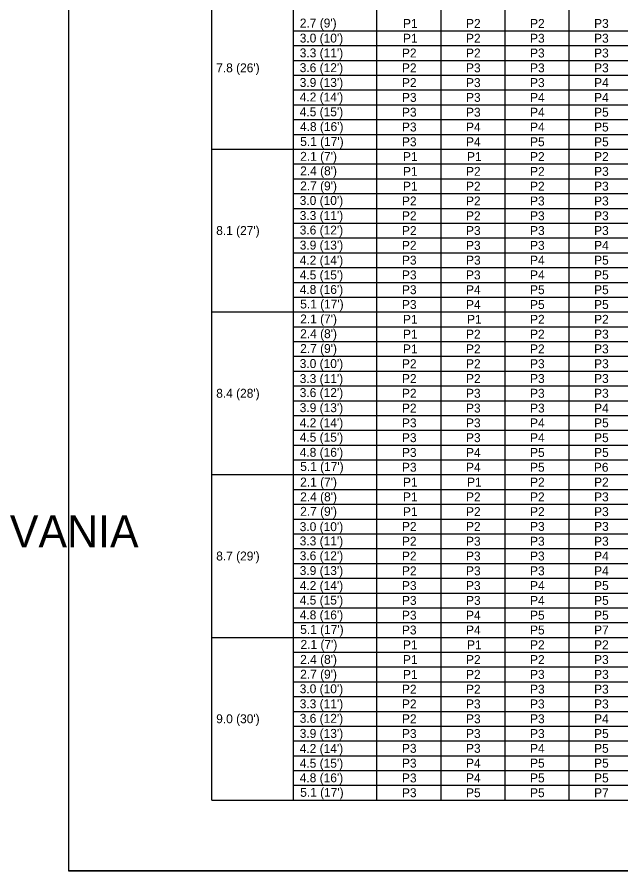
# Model space of a CAD drawing. Extents: x 637580 to 641008, y 294594 to 295782.
# Drawn here: x 640126.1 to 640328.9, y 295202.6 to 295489.6 of the extents above; entities that cross this region are included whole.
import ezdxf

# ---------------------------------------------------------------- set-up
doc = ezdxf.new("R2010")
doc.units = 0
doc.layers.add('1', color=7, linetype='Continuous')
doc.layers.add('2', color=7, linetype='Continuous')

msp = doc.modelspace()

# ---------------------------------------------------------------- linework, layer by layer
at = {"layer": '1'}
for p, q in [((640143.31, 295766.63), (640143.31, 295202.63)), ((640191.43, 295226.43), (640191.43, 295743.08)), ((640218.95, 295226.43), (640218.95, 295735.41)), ((640191.43, 295445.22), (640526.66, 295445.22)), ((640191.43, 295390.52), (640526.66, 295390.52)), ((640191.43, 295335.82), (640526.66, 295335.82)), ((640191.43, 295281.12), (640526.66, 295281.12)), ((640191.43, 295226.43), (640526.66, 295226.43)), ((640929.31, 295202.63), (640143.31, 295202.63)), ((640143.31, 295202.63), (640729.31, 295202.63))]:
    msp.add_line(p, q, dxfattribs=at)
at = {"layer": '2'}
for p, q in [((640246.95, 295226.43), (640246.95, 295735.41)), ((640268.47, 295226.43), (640268.47, 295728.06)), ((640289.99, 295226.43), (640289.99, 295728.06)), ((640311.5, 295226.43), (640311.5, 295728.06)), ((640218.95, 295485), (640526.66, 295485)), ((640218.95, 295480.02), (640526.66, 295480.02)), ((640218.95, 295475.05), (640526.66, 295475.05)), ((640218.95, 295470.08), (640526.66, 295470.08)), ((640218.95, 295465.11), (640526.66, 295465.11)), ((640218.95, 295460.13), (640526.66, 295460.13)), ((640218.95, 295455.16), (640526.66, 295455.16)), ((640218.95, 295450.19), (640526.66, 295450.19)), ((640218.95, 295440.24), (640526.66, 295440.24)), ((640218.95, 295435.27), (640526.66, 295435.27)), ((640218.95, 295430.3), (640526.66, 295430.3)), ((640218.95, 295425.33), (640526.66, 295425.33)), ((640218.95, 295420.35), (640526.66, 295420.35)), ((640218.95, 295415.38), (640526.66, 295415.38)), ((640218.95, 295410.41), (640526.66, 295410.41)), ((640218.95, 295405.44), (640526.66, 295405.44)), ((640218.95, 295400.46), (640526.66, 295400.46)), ((640218.95, 295395.49), (640526.66, 295395.49)), ((640218.95, 295385.55), (640526.66, 295385.55)), ((640218.95, 295380.57), (640526.66, 295380.57)), ((640218.95, 295375.6), (640526.66, 295375.6)), ((640218.95, 295370.63), (640526.66, 295370.63)), ((640218.95, 295365.66), (640526.66, 295365.66)), ((640218.95, 295360.68), (640526.66, 295360.68)), ((640218.95, 295355.71), (640526.66, 295355.71)), ((640218.95, 295350.74), (640526.66, 295350.74)), ((640218.95, 295345.77), (640526.66, 295345.77)), ((640218.95, 295340.79), (640526.66, 295340.79)), ((640218.95, 295330.85), (640526.66, 295330.85)), ((640218.95, 295325.88), (640526.66, 295325.88)), ((640218.95, 295320.9), (640526.66, 295320.9)), ((640218.95, 295315.93), (640526.66, 295315.93)), ((640218.95, 295310.96), (640526.66, 295310.96)), ((640218.95, 295305.99), (640526.66, 295305.99)), ((640218.95, 295301.01), (640526.66, 295301.01)), ((640218.95, 295296.04), (640526.66, 295296.04)), ((640218.95, 295291.07), (640526.66, 295291.07)), ((640218.95, 295286.1), (640526.66, 295286.1)), ((640218.95, 295276.15), (640526.66, 295276.15)), ((640218.95, 295271.18), (640526.66, 295271.18)), ((640218.95, 295266.21), (640526.66, 295266.21)), ((640218.95, 295261.23), (640526.66, 295261.23)), ((640218.95, 295256.26), (640526.66, 295256.26)), ((640218.95, 295251.29), (640526.66, 295251.29)), ((640218.95, 295246.32), (640526.66, 295246.32)), ((640218.95, 295241.34), (640526.66, 295241.34)), ((640218.95, 295236.37), (640526.66, 295236.37)), ((640218.95, 295231.4), (640526.66, 295231.4))]:
    msp.add_line(p, q, dxfattribs=at)

# ---------------------------------------------------------------- texts
at = {"layer": '1'}
for s, height, p in [("2.7 (9')", 3, (640221.04, 295486.11)), ('P1', 3, (640255.7, 295485.98)), ('P2', 3, (640276.88, 295485.98)), ('P2', 3, (640298.39, 295485.98)), ('P3', 3, (640319.91, 295485.98)), ("3.0 (10')", 3, (640221.01, 295481.06)), ('P1', 3, (640255.7, 295481.01)), ('P2', 3, (640276.88, 295481.01)), ('P3', 3, (640298.39, 295481.01)), ('P3', 3, (640319.91, 295481.01)), ("3.3 (11')", 3, (640221.01, 295476.08)), ('P2', 3, (640255.36, 295476.04)), ('P2', 3, (640276.88, 295476.04)), ('P3', 3, (640298.39, 295476.04)), ('P3', 3, (640319.91, 295476.04)), ("3.6 (12')", 3, (640221.01, 295471.11)), ("7.8 (26')", 3, (640192.95, 295471.06)), ('P2', 3, (640255.36, 295471.06)), ('P3', 3, (640276.88, 295471.06)), ('P3', 3, (640298.39, 295471.06)), ('P3', 3, (640319.91, 295471.06)), ("3.9 (13')", 3, (640221.01, 295466.14)), ('P2', 3, (640255.36, 295466.09)), ('P3', 3, (640276.88, 295466.09)), ('P3', 3, (640298.39, 295466.09)), ('P4', 3, (640319.91, 295466.09)), ("4.2 (14')", 3, (640221.01, 295461.25)), ('P3', 3, (640255.36, 295461.12)), ('P3', 3, (640276.88, 295461.12)), ('P4', 3, (640298.39, 295461.12)), ('P4', 3, (640319.91, 295461.12)), ("4.5 (15')", 3, (640221.01, 295456.28)), ('P3', 3, (640255.36, 295456.15)), ('P3', 3, (640276.88, 295456.15)), ('P4', 3, (640298.39, 295456.15)), ('P5', 3, (640319.91, 295456.15)), ("4.8 (16')", 3, (640221.1, 295451.3)), ('P3', 3, (640255.36, 295451.17)), ('P4', 3, (640276.88, 295451.17)), ('P4', 3, (640298.39, 295451.17)), ('P5', 3, (640319.91, 295451.17)), ("5.1 (17')", 3, (640221.17, 295446.28)), ('P3', 3, (640255.36, 295446.2)), ('P4', 3, (640276.88, 295446.2)), ('P5', 3, (640298.39, 295446.2)), ('P5', 3, (640319.91, 295446.2)), ("2.1 (7')", 3, (640221.16, 295441.31)), ('P1', 3, (640255.7, 295441.23)), ('P1', 3, (640277.22, 295441.23)), ('P2', 3, (640298.39, 295441.23)), ('P2', 3, (640319.91, 295441.23)), ("2.4 (8')", 3, (640221.16, 295436.43)), ('P1', 3, (640255.7, 295436.26)), ('P2', 3, (640276.88, 295436.26)), ('P2', 3, (640298.39, 295436.26)), ('P3', 3, (640319.91, 295436.26)), ("2.7 (9')", 3, (640221.16, 295431.37)), ('P1', 3, (640255.7, 295431.28)), ('P2', 3, (640276.88, 295431.28)), ('P2', 3, (640298.39, 295431.28)), ('P3', 3, (640319.91, 295431.28)), ("3.0 (10')", 3, (640221.01, 295426.48)), ('P2', 3, (640255.36, 295426.31)), ('P2', 3, (640276.88, 295426.31)), ('P3', 3, (640298.39, 295426.31)), ('P3', 3, (640319.91, 295426.31)), ("3.3 (11')", 3, (640221.01, 295421.43)), ('P2', 3, (640255.36, 295421.34)), ('P2', 3, (640276.88, 295421.34)), ('P3', 3, (640298.39, 295421.34)), ('P3', 3, (640319.91, 295421.34)), ("8.1 (27')", 3, (640192.95, 295416.37)), ("3.6 (12')", 3, (640221.01, 295416.54)), ('P2', 3, (640255.36, 295416.37)), ('P3', 3, (640276.88, 295416.37)), ('P3', 3, (640298.39, 295416.37)), ('P3', 3, (640319.91, 295416.37)), ("3.9 (13')", 3, (640221.01, 295411.48)), ('P2', 3, (640255.36, 295411.39)), ('P3', 3, (640276.88, 295411.39)), ('P3', 3, (640298.39, 295411.39)), ('P4', 3, (640319.91, 295411.39)), ("4.2 (14')", 3, (640221.01, 295406.43)), ('P3', 3, (640255.36, 295406.42)), ('P3', 3, (640276.88, 295406.42)), ('P4', 3, (640298.39, 295406.42)), ('P5', 3, (640319.91, 295406.42)), ("4.5 (15')", 3, (640221.01, 295401.45)), ('P3', 3, (640255.36, 295401.45)), ('P3', 3, (640276.88, 295401.45)), ('P4', 3, (640298.39, 295401.45)), ('P5', 3, (640319.91, 295401.45)), ("4.8 (16')", 3, (640221.01, 295396.57)), ('P3', 3, (640255.36, 295396.48)), ('P4', 3, (640276.88, 295396.48)), ('P5', 3, (640298.39, 295396.48)), ('P5', 3, (640319.91, 295396.48)), ("5.1 (17')", 3, (640221.17, 295391.67)), ('P3', 3, (640255.36, 295391.5)), ('P4', 3, (640276.88, 295391.5)), ('P5', 3, (640298.39, 295391.5)), ('P5', 3, (640319.91, 295391.5)), ("2.1 (7')", 3, (640221.16, 295386.65)), ('P1', 3, (640255.7, 295386.53)), ('P1', 3, (640277.22, 295386.53)), ('P2', 3, (640298.39, 295386.53)), ('P2', 3, (640319.91, 295386.53)), ("2.4 (8')", 3, (640221.16, 295381.69)), ('P1', 3, (640255.7, 295381.56)), ('P2', 3, (640276.88, 295381.56)), ('P2', 3, (640298.39, 295381.56)), ('P3', 3, (640319.91, 295381.56)), ("2.7 (9')", 3, (640221.16, 295376.72)), ('P1', 3, (640255.7, 295376.59)), ('P2', 3, (640276.88, 295376.59)), ('P2', 3, (640298.39, 295376.59)), ('P3', 3, (640319.91, 295376.59)), ("3.0 (10')", 3, (640221.01, 295371.66)), ('P2', 3, (640255.36, 295371.61)), ('P2', 3, (640276.88, 295371.61)), ('P3', 3, (640298.39, 295371.61)), ('P3', 3, (640319.91, 295371.61)), ("3.3 (11')", 3, (640221.01, 295366.61)), ('P2', 3, (640255.36, 295366.64)), ('P2', 3, (640276.88, 295366.64)), ('P3', 3, (640298.39, 295366.64)), ('P3', 3, (640319.91, 295366.64)), ("8.4 (28')", 3, (640192.95, 295361.67)), ("3.6 (12')", 3, (640221.01, 295361.89)), ('P2', 3, (640255.36, 295361.67)), ('P3', 3, (640276.88, 295361.67)), ('P3', 3, (640298.39, 295361.67)), ('P3', 3, (640319.91, 295361.67)), ("3.9 (13')", 3, (640221.01, 295356.83)), ('P2', 3, (640255.36, 295356.7)), ('P3', 3, (640276.88, 295356.7)), ('P3', 3, (640298.39, 295356.7)), ('P4', 3, (640319.91, 295356.7)), ("4.2 (14')", 3, (640221.01, 295351.77)), ('P3', 3, (640255.36, 295351.72)), ('P3', 3, (640276.88, 295351.72)), ('P4', 3, (640298.39, 295351.72)), ('P5', 3, (640319.91, 295351.72)), ("4.5 (15')", 3, (640221.01, 295346.88)), ('P3', 3, (640255.36, 295346.75)), ('P3', 3, (640276.88, 295346.75)), ('P4', 3, (640298.39, 295346.75)), ('P5', 3, (640319.91, 295346.75)), ("4.8 (16')", 3, (640221.01, 295341.83)), ('P3', 3, (640255.36, 295341.78)), ('P4', 3, (640276.88, 295341.78)), ('P5', 3, (640298.39, 295341.78)), ('P5', 3, (640319.91, 295341.78)), ("5.1 (17')", 3, (640221.17, 295337.05)), ('P3', 3, (640255.36, 295336.81)), ('P4', 3, (640276.88, 295336.81)), ('P5', 3, (640298.39, 295336.81)), ('P6', 3, (640319.83, 295336.81)), ("2.1 (7')", 3, (640221.16, 295331.83)), ('P1', 3, (640255.7, 295331.83)), ('P1', 3, (640277.22, 295331.83)), ('P2', 3, (640298.39, 295331.83)), ('P2', 3, (640319.91, 295331.83)), ("2.4 (8')", 3, (640221.16, 295326.87)), ('P1', 3, (640255.7, 295326.86)), ('P2', 3, (640276.88, 295326.86)), ('P2', 3, (640298.39, 295326.86)), ('P3', 3, (640319.91, 295326.86)), ("2.7 (9')", 3, (640221.16, 295321.98)), ('COMMONWEALTH OF PENNSYLVANIA', 10.7828, (639900.9, 295311.36)), ('P1', 3, (640255.7, 295321.89)), ('P2', 3, (640276.88, 295321.89)), ('P2', 3, (640298.39, 295321.89)), ('P3', 3, (640319.91, 295321.89)), ("3.0 (10')", 3, (640221.01, 295316.84)), ('P2', 3, (640255.36, 295316.92)), ('P2', 3, (640276.88, 295316.92)), ('P3', 3, (640298.39, 295316.92)), ('P3', 3, (640319.91, 295316.92)), ("3.3 (11')", 3, (640221.01, 295312.04)), ('P2', 3, (640255.36, 295311.94)), ('P3', 3, (640276.88, 295311.94)), ('P3', 3, (640298.39, 295311.94)), ('P3', 3, (640319.91, 295311.94)), ("8.7 (29')", 3, (640192.95, 295306.97)), ("3.6 (12')", 3, (640221.01, 295307.06)), ('P2', 3, (640255.36, 295306.97)), ('P3', 3, (640276.88, 295306.97)), ('P3', 3, (640298.39, 295306.97)), ('P4', 3, (640319.91, 295306.97)), ("3.9 (13')", 3, (640221.01, 295302.09)), ('P2', 3, (640255.36, 295302)), ('P3', 3, (640276.88, 295302)), ('P3', 3, (640298.39, 295302)), ('P4', 3, (640319.91, 295302)), ("4.2 (14')", 3, (640221.01, 295297.03)), ('P3', 3, (640255.36, 295297.03)), ('P3', 3, (640276.88, 295297.03)), ('P4', 3, (640298.39, 295297.03)), ('P5', 3, (640319.91, 295297.03)), ("4.5 (15')", 3, (640221.01, 295292.15)), ('P3', 3, (640255.36, 295292.05)), ('P3', 3, (640276.88, 295292.05)), ('P4', 3, (640298.39, 295292.05)), ('P5', 3, (640319.91, 295292.05)), ("4.8 (16')", 3, (640221.01, 295287.17)), ('P3', 3, (640255.36, 295287.08)), ('P4', 3, (640276.88, 295287.08)), ('P5', 3, (640298.39, 295287.08)), ('P5', 3, (640319.91, 295287.08)), ("5.1 (17')", 3, (640221.17, 295282.28)), ('P3', 3, (640255.36, 295282.11)), ('P4', 3, (640276.88, 295282.11)), ('P5', 3, (640298.39, 295282.11)), ('P7', 3, (640319.91, 295282.11)), ("2.1 (7')", 3, (640221.28, 295277.26)), ('P1', 3, (640255.7, 295277.14)), ('P1', 3, (640277.22, 295277.14)), ('P2', 3, (640298.39, 295277.14)), ('P2', 3, (640319.91, 295277.14)), ("2.4 (8')", 3, (640221.16, 295272.22)), ('P1', 3, (640255.7, 295272.16)), ('P2', 3, (640276.88, 295272.16)), ('P2', 3, (640298.39, 295272.16)), ('P3', 3, (640319.91, 295272.16)), ("2.7 (9')", 3, (640221.16, 295267.24)), ('P1', 3, (640255.7, 295267.19)), ('P2', 3, (640276.88, 295267.19)), ('P3', 3, (640298.39, 295267.19)), ('P3', 3, (640319.91, 295267.19)), ("3.0 (10')", 3, (640221.01, 295262.35)), ('P2', 3, (640255.36, 295262.22)), ('P2', 3, (640276.88, 295262.22)), ('P3', 3, (640298.39, 295262.22)), ('P3', 3, (640319.91, 295262.22)), ("3.3 (11')", 3, (640221.01, 295257.3)), ('P2', 3, (640255.36, 295257.25)), ('P3', 3, (640276.88, 295257.25)), ('P3', 3, (640298.39, 295257.25)), ('P3', 3, (640319.91, 295257.25)), ("9.0 (30')", 3, (640192.95, 295252.27)), ("3.6 (12')", 3, (640221.01, 295252.41)), ('P2', 3, (640255.36, 295252.27)), ('P3', 3, (640276.88, 295252.27)), ('P3', 3, (640298.39, 295252.27)), ('P4', 3, (640319.91, 295252.27)), ("3.9 (13')", 3, (640221.01, 295247.35)), ('P3', 3, (640255.36, 295247.3)), ('P3', 3, (640276.88, 295247.3)), ('P3', 3, (640298.39, 295247.3)), ('P5', 3, (640319.91, 295247.3)), ("4.2 (14')", 3, (640221.01, 295242.3)), ('P3', 3, (640255.36, 295242.33)), ('P3', 3, (640276.88, 295242.33)), ('P4', 3, (640298.39, 295242.33)), ('P5', 3, (640319.91, 295242.33)), ("4.5 (15')", 3, (640221.01, 295237.32)), ('P3', 3, (640255.36, 295237.36)), ('P4', 3, (640276.88, 295237.36)), ('P5', 3, (640298.39, 295237.36)), ('P5', 3, (640319.91, 295237.36)), ("4.8 (16')", 3, (640221.01, 295232.44)), ('P3', 3, (640255.36, 295232.38)), ('P4', 3, (640276.88, 295232.38)), ('P5', 3, (640298.39, 295232.38)), ('P5', 3, (640319.91, 295232.38)), ("5.1 (17')", 3, (640221.17, 295227.54)), ('P3', 3, (640255.36, 295227.41)), ('P5', 3, (640276.88, 295227.41)), ('P5', 3, (640298.39, 295227.41)), ('P7', 3, (640319.91, 295227.41))]:
    msp.add_text(s, height=height, dxfattribs=at).set_placement(p)

doc.saveas('drawing.dxf')
